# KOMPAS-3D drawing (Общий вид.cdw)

Referenced files in E:\диплом 1\Дипломы для Сидоренко\Олейник\чертежи на рапечатку\А1\: 23110 ГотовыйМне1.tif, 23110 ГотовыйМне2.tif
Referenced files: Общий вид 23-110 (1).cdw
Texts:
  земснаряд
  Текст на чертеже
  Размерные надписи
  Шероховатость
  Линия-выноска #1
  Линия-выноска #2
  Линия-выноска #3
  Отклонения формы и база
  Заголовок таблицы
  Ячейка таблицы
  Стрелка вида
  Обозначение изменения
  Фигурная скобка
  Номер узла
  Марка координационной оси
  VRCB
  Выносная надпись
  Обозначение узла
  Марка/позиционное обозначение с линией-выноской
  Марка/позиционное обозначение на линии
  Марка/позиционное обозначение без линии-выноски
  План главной палубы
  Поз
  Обознач
  Кол
  Общ
  Примеч
  Лебедка становая
  Лебедка папильонажная
  Всасывающий трубопровод
  Нагнетательный трубопровод
  Демонт.
  Матюшко А.Н.
Dimensions and other numbers on the sheet: 7; 1; 2; 3; 4; 5; 6; 0; 8; 9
